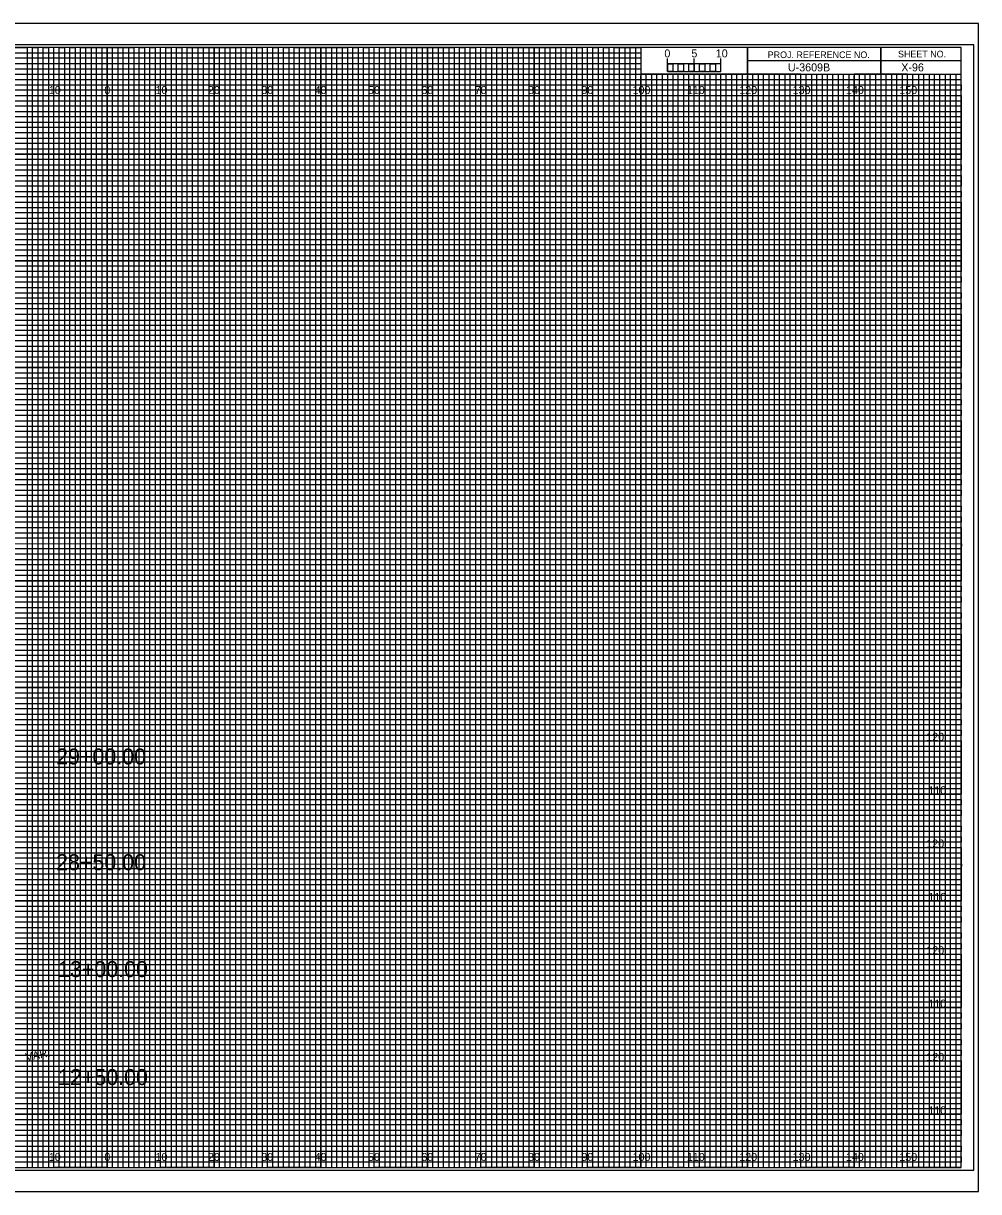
# Model space of a CAD drawing. Extents: x -13 to 323, y -5 to 215.
# Drawn here: x 144.3 to 323.3, y -4.5 to 214.5 of the extents above; entities that cross this region are included whole.
import ezdxf

# ---------------------------------------------------------------- set-up
doc = ezdxf.new("R2010")
doc.units = 0
for name, color, linetype in [('Prop XS Bar Scale Labels', 7, 'Continuous'), ('Prop XS Elevation Labels', 7, 'Continuous'), ('Prop XS Offset Labels', 7, 'Continuous'), ('Prop XS Project Number', 7, 'Continuous'), ('Prop XS Sheet Number', 7, 'Continuous'), ('Prop XS Side Slope Text', 7, 'Continuous'), ('Prop XS Station Labels', 7, 'Continuous'), ('Sheet Cross Section CELL', 7, 'Continuous'), ('Sheet Cross Section Grid Major CELL', 7, 'Continuous'), ('Sheet Cross Section Grid Middle CELL', 7, 'Continuous'), ('Sheet Cross Section Grid Minor 1 CELL', 7, 'Continuous'), ('Sheet Cross Section Grid Minor 2 CELL', 7, 'Continuous'), ('Sheet Cross Section Scale CELL', 7, 'Continuous'), ('Sheet Cutting Line CELL', 7, 'Continuous'), ('Sheet DOT Grid CELL', 7, 'Continuous'), ('Sheet Plot Border Inside CELL', 7, 'Continuous'), ('Sheet Plot Border Outside CELL', 7, 'Continuous')]:
    doc.layers.add(name, color=color, linetype=linetype)

msp = doc.modelspace()

# ---------------------------------------------------------------- linework, layer by layer
at = {"layer": 'Sheet Cross Section CELL'}
for p, q in [((305, 210), (305, 205)), ((305, 205), (305, 210)), ((280, 207.5), (280, 205)), ((320, 207.49), (280, 207.49)), ((280, 205), (320, 205))]:
    msp.add_line(p, q, dxfattribs=at)
for points in [[(320, 210), (0, 210), (0, 0), (320, 0)], [(280, 210), (260, 210), (260, 205.03), (280, 205.03)], [(320, 210), (280, 210), (280, 205), (320, 205)]]:
    msp.add_lwpolyline(points, close=True, dxfattribs=at)
at = {"layer": 'Sheet Cross Section Grid Major CELL'}
for p, q in [((150, 210), (140, 210)), ((150, 0), (150, 210)), ((170, 210), (160, 210)), ((160, 210), (160, 0)), ((170, 0), (170, 210)), ((190, 210), (180, 210)), ((180, 210), (180, 0)), ((190, 0), (190, 210)), ((210, 210), (200, 210)), ((200, 210), (200, 0)), ((210, 0), (210, 210)), ((230, 210), (220, 210)), ((220, 210), (220, 0)), ((230, 0), (230, 210)), ((250, 210), (240, 210)), ((240, 210), (240, 0)), ((250, 0), (250, 210)), ((260, 210), (260, 0)), ((270, 0), (270, 205)), ((290, 205), (280, 205)), ((280, 205), (280, 0)), ((290, 0), (290, 205)), ((310, 205), (300, 205)), ((300, 205), (300, 0)), ((310, 0), (310, 205)), ((160, 0), (150, 0)), ((180, 0), (170, 0)), ((200, 0), (190, 0)), ((220, 0), (210, 0)), ((240, 0), (230, 0)), ((260, 0), (250, 0)), ((280, 0), (270, 0)), ((300, 0), (290, 0)), ((320, 0), (310, 0)), ((320, 0), (320, 0))]:
    msp.add_line(p, q, dxfattribs=at)
for points in [[(0, 200), (320, 200), (320, 190), (0, 190)], [(0, 180), (320, 180), (320, 170), (0, 170)], [(0, 160), (320, 160), (320, 150), (0, 150)], [(0, 140), (320, 140), (320, 130), (0, 130)], [(0, 120), (320, 120), (320, 110), (0, 110)], [(0, 100), (320, 100), (320, 90), (0, 90)], [(0, 80), (320, 80), (320, 70), (0, 70)], [(0, 60), (320, 60), (320, 50), (0, 50)], [(0, 40), (320, 40), (320, 30), (0, 30)], [(0, 20), (320, 20), (320, 10), (0, 10)]]:
    msp.add_lwpolyline(points, dxfattribs=at)
at = {"layer": 'Sheet Cross Section Grid Middle CELL'}
for points in [[(135, 210), (145, 210), (145, 0), (155, 0), (155, 210), (165, 210), (165, 0), (175, 0), (175, 210), (185, 210), (185, 0), (195, 0), (195, 210), (205, 210), (205, 0), (215, 0), (215, 210), (225, 210), (225, 0), (235, 0), (235, 210), (245, 210), (245, 0), (255, 0), (255, 210), (259.93, 210), (260, 210), (260, 205), (264.99, 205), (264.99, 0), (275, 0), (275, 205), (285, 205), (285, 0), (295, 0), (295, 205), (305, 205), (305, 0), (315, 0), (315, 205)], [(0, 205), (275, 205)], [(0, 185), (320, 185), (320, 195), (0, 195)], [(0, 165), (320, 165), (320, 175), (0, 175)], [(0, 145), (320, 145), (320, 155), (0, 155)], [(0, 125), (320, 125), (320, 135), (0, 135)], [(0, 105), (320, 105), (320, 115), (0, 115)], [(0, 85), (320, 85), (320, 95), (0, 95)], [(0, 65), (320, 65), (320, 75), (0, 75)], [(0, 45), (320, 45), (320, 55), (0, 55)], [(0, 25), (320, 25), (320, 35), (0, 35)], [(0, 5), (320, 5), (320, 15), (0, 15)]]:
    msp.add_lwpolyline(points, dxfattribs=at)
at = {"layer": 'Sheet Cross Section Grid Minor 1 CELL'}
for p, q in [((0, 209), (260, 209)), ((260, 209), (260, 207.98)), ((260, 207.98), (0, 207.98)), ((0, 207), (260, 207)), ((260, 205.89), (0, 205.89)), ((260, 207), (260, 205.89)), ((0, 204), (320, 204))]:
    msp.add_line(p, q, dxfattribs=at)
for points in [[(0, 203), (270, 203), (320, 203), (320, 202), (0, 202)], [(0, 201), (320, 201), (320, 199), (0, 199)], [(0, 198), (320, 198), (320, 197), (0, 196.98)], [(0, 196), (320, 196), (320, 194), (0, 194)], [(0, 193), (320, 193), (320, 192), (0, 192)], [(0, 191), (320, 191), (320, 189), (0, 189)], [(0, 188), (320, 188), (320, 187), (0, 187)], [(0, 186), (320, 186), (320, 184), (0, 184)], [(0, 183), (320, 183), (320, 182), (0, 182)], [(0, 181), (320, 181), (320, 179), (0, 179)], [(0, 178), (320, 178), (320, 177), (0, 177)], [(0, 176), (320, 176), (320, 173.95), (320, 173), (320, 172), (0, 172)], [(0, 174), (320, 174), (320, 173), (0, 173)], [(0, 171), (320, 171), (320, 169), (0, 169.03)], [(0, 169.03), (320, 169), (320, 168), (0, 168)], [(0, 167), (320, 167), (320, 166), (0, 166)], [(0, 164), (320, 164), (320, 163), (0, 163)], [(0, 162), (320, 162), (320, 161), (0, 161)], [(-0.07, 158.89), (320, 158.89), (320, 157.88), (-0.07, 157.88)], [(0, 157), (320, 157), (320, 156), (0, 156)], [(0, 154), (320, 154), (320, 153), (0, 153)], [(0, 152), (320, 152), (320, 151), (0, 151)], [(0, 149), (320, 149), (320, 148), (0, 148)], [(0, 147), (320, 147), (320, 146), (0, 146)], [(0, 144), (320, 144), (320, 143), (0, 143)], [(0, 142), (320, 142), (320, 141), (0, 141)], [(0, 139), (320, 139), (319.99, 137.98), (0, 138)], [(0, 137), (320, 137), (320, 136), (0, 136)], [(0, 134), (320, 134), (320, 133), (0, 133)], [(0, 132), (320, 132), (320, 131), (0, 131)], [(0, 129), (320, 129), (320, 128), (0, 128)], [(0, 127), (320, 127), (320, 126), (0, 126)], [(0, 124), (320, 124), (320, 123), (0, 123)], [(0, 122), (320, 122), (320, 121), (0, 121)], [(0, 119), (320, 119), (320, 118), (0, 118)], [(0, 116.99), (320.07, 116.91), (320, 116), (0, 116)], [(0, 114), (320, 114), (320, 113), (0, 113)], [(0, 112), (320, 112), (320, 111), (0, 111)], [(0, 109), (320, 109), (320, 108), (0, 108)], [(0, 107), (320, 107), (320, 106), (0, 106)], [(0, 104), (320, 104), (320, 103), (0, 103)], [(0, 102), (320, 102), (320, 101), (0, 101)], [(0, 99), (320, 99), (320, 98), (0, 98)], [(0, 97), (320, 97), (320, 96), (0, 96)], [(0, 94), (320, 94), (320, 93), (0, 93)], [(0, 92), (320, 92), (320, 91), (0, 91)], [(0, 89), (320, 89), (320, 88), (0, 88)], [(0, 87), (320, 87), (320, 86), (0, 86)], [(0, 84), (320, 84), (320, 83), (0, 83)], [(0, 82), (320, 82), (320, 81), (0, 81)], [(0, 79), (320, 79), (319.99, 77.98), (0, 78)], [(0, 77), (320, 77), (320, 76), (0, 76)], [(0, 74), (320, 74), (320, 73), (0, 73)], [(0, 72), (320, 72), (320, 71), (0, 71)], [(0, 69), (320, 69), (320, 68), (0, 68)], [(0, 67), (320, 67), (320, 66), (0, 66)], [(0, 64), (320, 64), (320, 63), (0, 63)], [(0, 62), (320, 62), (320, 61), (0, 61)], [(0, 59), (320, 59), (320, 58), (0, 58)], [(0, 56.99), (320.07, 56.91), (320, 56), (0, 56)], [(0, 54), (320, 54), (320, 53), (0, 53)], [(0, 52), (320, 52), (320, 51), (0, 51)], [(0, 49), (320, 49), (320, 48), (0, 48)], [(0, 47), (320, 47), (320, 46), (0, 46)], [(0, 44), (320, 44), (320, 43), (0, 43)], [(0, 42), (320, 42), (320, 41), (0, 41)], [(0, 39), (320, 39), (320, 38), (0, 38)], [(0, 37), (320, 37), (320, 36), (0, 36)], [(0, 34), (320, 34), (320, 33), (0, 33)], [(0, 32), (320, 32), (320, 31), (0, 31)], [(0, 29), (320, 29), (320, 28), (0, 28)], [(0, 27), (320, 27), (320, 26), (0, 26)], [(0, 24), (320, 24), (320, 23), (0, 23)], [(0, 22), (320, 22), (320, 21), (0, 21)], [(0, 19), (320, 19), (320, 18), (0, 18)], [(0, 17), (320, 17), (320, 16), (0, 16)], [(0, 14), (320, 14), (320, 13), (0, 13)], [(0, 12), (320, 12), (320, 11), (0, 11)], [(0, 9), (320, 9), (320, 8), (0, 8)], [(0, 7), (320, 7), (320, 6), (0, 6)], [(0, 4), (320, 4), (320, 3), (0, 3)], [(0, 2), (320, 2), (320, 1), (0, 1)]]:
    msp.add_lwpolyline(points, dxfattribs=at)
at = {"layer": 'Sheet Cross Section Grid Minor 2 CELL'}
for p, q in [((267, 205), (266.01, 205)), ((266.01, 205), (266.01, 0)), ((267, 0), (267, 205)), ((269, 205), (268, 205)), ((268, 205), (268, 0)), ((269, 0), (269, 205)), ((266.01, 0), (265, 0)), ((268, 0), (267, 0))]:
    msp.add_line(p, q, dxfattribs=at)
for points in [[(145, 0), (146, 0), (146, 210), (147, 210), (147, 0)], [(147, 0), (148, 0), (148, 210), (149, 210), (149, 0)], [(150, 0), (151, 0), (151, 210), (152, 210), (152, 0)], [(152, 0), (153, 0), (153, 210), (154, 210), (154, 0)], [(155, 0), (156, 0), (156, 210), (157, 210), (157, 0)], [(157, 0), (158, 0), (158, 210), (159, 210), (159, 0)], [(160, 0), (161, 0), (161, 210), (162, 210), (162, 0)], [(162, 0), (163, 0), (163, 210), (164, 210), (164, 0)], [(165, 0), (166, 0), (166, 210), (167, 210), (167, 0)], [(167, 0), (168, 0), (168, 210), (169, 210), (169, 0)], [(170, 0), (171, 0), (171, 210), (172, 210), (172, 0)], [(172, 0), (173, 0), (173, 210), (174, 210), (174, 0)], [(175, 0), (176, 0), (176, 210), (177, 210), (177, 0)], [(177, 0), (178, 0), (178, 210), (179, 210), (179, 0)], [(180, 0), (181, 0), (181, 210), (182, 210), (182, 0)], [(182, 0), (183, 0), (183, 210), (184, 210), (184, 0)], [(185, 0), (186, 0), (186, 210), (187, 210), (187, 0)], [(187, 0), (188, 0), (188, 210), (189, 210), (189, 0)], [(190, 0), (191, 0), (191, 210), (192, 210), (192, 0)], [(192, 0), (193, 0), (193, 210), (194, 210), (194, 0)], [(195, 0), (196, 0), (196, 210), (197, 210), (197, 0)], [(197, 0), (198, 0), (198, 210), (199, 210), (199, 0)], [(200, 0), (201, 0), (201, 210), (202, 210), (202, 0)], [(202, 0), (203, 0), (203, 210), (204, 210), (204, 0)], [(205, 0), (206, 0), (206, 210), (207, 210), (207, 0)], [(207, 0), (208, 0), (208, 210), (209, 210), (209, 0)], [(210, 0), (211, 0), (211, 210), (212, 210), (212, 0)], [(212, 0), (213, 0), (213, 210), (214, 210), (214, 0)], [(215, 0), (216, 0), (216, 210), (217, 210), (217, 0)], [(217, 0), (218, 0), (218, 210), (219, 210), (219, 0)], [(220, 0), (221, 0), (221, 210), (222, 210), (222, 0)], [(222, 0), (223, 0), (223, 210), (224, 210), (224, 0)], [(225, 0), (226, 0), (226, 210), (227, 210), (227, 0)], [(227, 0), (228, 0), (228, 210), (229, 210), (229, 0)], [(230, 0), (231, 0), (231, 210), (232, 210), (232, 0)], [(232, 0), (233, 0), (233, 210), (234, 210), (234, 0)], [(235, 0), (236, 0), (236, 210), (237, 210), (237, 0)], [(237, 0), (238, 0), (238, 210), (239, 210), (239, 0)], [(240, 0), (241, 0), (241, 210), (242, 210), (242, 0)], [(242, 0), (243, 0), (243, 210), (244, 210), (244, 0)], [(245, 0), (246, 0), (246, 210), (247, 210), (247, 0)], [(247, 0), (248, 0), (248, 210), (249, 210), (249, 0)], [(250, 0), (251, 0), (251, 210), (252, 210), (252, 0)], [(252, 0), (253, 0), (253, 210), (254, 210), (254, 0)], [(255, 0), (256, 0), (256, 210), (257, 210), (257, 0)], [(257, 0), (258, 0), (258, 210), (259, 210), (259, 0)], [(260, 0), (261, 0), (261, 205), (262.02, 205), (262.02, 0)], [(262, 0), (263, 0), (263, 205), (263.99, 205), (263.99, 0)], [(270, 0), (270.98, 0), (270.98, 205), (272, 205), (272, 0)], [(272, 0), (273, 0), (273, 205), (274.05, 205), (274.05, 0)], [(275, 0), (276, 0), (276, 205), (277, 205), (277, 0)], [(277, 0), (278, 0), (278, 205), (279, 205), (279, 0)], [(280, 0), (281, 0), (281, 205), (282, 205), (282, 0)], [(282, 0), (283, 0), (283, 205), (284, 205), (284, 0)], [(285, 0), (286, 0), (286, 205), (287, 205), (287, 0)], [(287, 0), (288, 0), (288, 205), (289, 205), (289, 0)], [(290, 0), (291, 0), (291, 205), (292, 205), (292, 0)], [(292, 0), (293, 0), (293, 205), (294, 205), (294, 0)], [(295, 0), (296, 0), (296, 205), (297, 205), (297, 0)], [(297, 0), (298, 0), (298, 205), (299, 205), (299, 0)], [(300, 0), (301, 0), (301, 205), (302, 205), (302, 0)], [(302, 0), (303, 0), (303, 205), (304, 205), (304, 0)], [(305, 0), (306, 0), (306, 205), (307, 205), (307, 0)], [(307, 0), (308, 0), (308, 205), (309, 205), (309, 0)], [(310, 0), (311, 0), (311, 205), (312, 205), (312, 0)], [(312, 0), (313, 0), (313, 205), (314, 205), (314, 0)], [(315, 0), (316, 0), (316, 205), (317, 205), (317, 0)], [(317, 0), (318, 0), (318, 205), (319, 205), (319, 0)]]:
    msp.add_lwpolyline(points, dxfattribs=at)
at = {"layer": 'Sheet Cross Section Scale CELL'}
for p, q in [((265, 205.49), (265, 207.9)), ((265, 206.9), (265, 207.9)), ((270, 205.49), (270, 207.9)), ((275, 205.49), (275, 207.9)), ((275, 206.9), (275, 207.9))]:
    msp.add_line(p, q, dxfattribs=at)
for points in [[(275, 206.9), (265, 206.9), (265, 205.49), (275, 205.49)], [(265, 206.9), (266, 206.9), (266, 205.49), (265, 205.49)], [(267, 206.9), (268, 206.9), (268, 205.49), (267, 205.49)], [(269, 206.9), (270, 206.9), (270, 205.49), (269, 205.49)], [(271, 206.9), (272, 206.9), (272, 205.49), (271, 205.49)], [(273, 206.9), (274, 206.9), (274, 205.49), (273, 205.49)]]:
    msp.add_lwpolyline(points, close=True, dxfattribs=at)
at = {"layer": 'Sheet Cutting Line CELL'}
for p, q in [((323.3, 214.5), (-13.4, 214.5)), ((-13.4, -4.5), (323.3, -4.5))]:
    msp.add_line(p, q, dxfattribs=at)
at = {"layer": 'Sheet DOT Grid CELL'}
for p, q in [((150, 0), (150, 210)), ((160, 0), (160, 210)), ((170, 0), (170, 210)), ((180, 0), (180, 210)), ((190, 0), (190, 210)), ((200, 0), (200, 210)), ((210, 0), (210, 210)), ((220, 0), (220, 210)), ((230, 0), (230, 210)), ((240, 0), (240, 210)), ((250, 0), (250, 210)), ((260, 0), (260, 204.69)), ((270, 0), (270, 204.69)), ((280, 0), (280, 204.69)), ((290, 0), (290, 204.69)), ((300, 0), (300, 204.69)), ((310, 0), (310, 204.69)), ((0, 200), (320, 200)), ((0, 190), (320, 190)), ((0, 180), (320, 180)), ((0, 170), (320, 170)), ((0, 160), (320, 160)), ((0, 150), (320, 150)), ((0, 140), (320, 140)), ((0, 130), (320, 130)), ((0, 120), (320, 120)), ((0, 110), (320, 110)), ((0, 100), (320, 100)), ((0, 90), (320, 90)), ((0, 80), (320, 80)), ((0, 70), (320, 70)), ((0, 60), (320, 60)), ((0, 50), (320, 50)), ((0, 40), (320, 40)), ((0, 30), (320, 30)), ((0, 20), (320, 20)), ((0, 10), (320, 10))]:
    msp.add_line(p, q, dxfattribs=at)
at = {"layer": 'Sheet Plot Border Inside CELL'}
msp.add_lwpolyline([(-10.8, -0.5), (322.4, -0.5), (322.4, 210.5), (-10.8, 210.5)], close=True, dxfattribs=at)
at = {"layer": 'Sheet Plot Border Outside CELL'}
msp.add_lwpolyline([(-13.4, -4.5), (323.3, -4.5), (323.3, 214.5), (-13.4, 214.5)], close=True, dxfattribs=at)

# ---------------------------------------------------------------- texts
at = {"layer": 'Prop XS Bar Scale Labels'}
for s, p in [('5', (269.47, 208.12)), ('10', (274.04, 208.12))]:
    msp.add_text(s, height=1.5, dxfattribs=at).set_placement(p)
at = {"layer": 'Prop XS Elevation Labels'}
for s, p in [('120', (313.5, 80)), ('110', (313.88, 70)), ('120', (313.5, 60)), ('110', (313.88, 50)), ('120', (313.5, 40)), ('110', (313.88, 30)), ('120', (313.5, 20)), ('110', (313.88, 10))]:
    msp.add_text(s, height=1.5, dxfattribs=at).set_placement(p)
at = {"layer": 'Prop XS Offset Labels'}
for s, p in [('10', (149.04, 201.25)), ('0', (159.45, 201.25)), ('0', (159.45, 201.25)), ('10', (169.04, 201.25)), ('20', (178.86, 201.25)), ('30', (188.86, 201.25)), ('40', (198.86, 201.25)), ('50', (208.86, 201.25)), ('60', (218.86, 201.25)), ('70', (228.86, 201.25)), ('80', (238.86, 201.25)), ('90', (248.86, 201.25)), ('100', (258.44, 201.25)), ('110', (268.62, 201.25)), ('120', (278.44, 201.25)), ('130', (288.44, 201.25)), ('140', (298.44, 201.25)), ('150', (308.44, 201.25)), ('10', (149.04, 1.25)), ('0', (159.45, 1.25)), ('0', (159.45, 1.25)), ('10', (169.04, 1.25)), ('20', (178.86, 1.25)), ('30', (188.86, 1.25)), ('40', (198.86, 1.25)), ('50', (208.86, 1.25)), ('60', (218.86, 1.25)), ('70', (228.86, 1.25)), ('80', (238.86, 1.25)), ('90', (248.86, 1.25)), ('100', (258.44, 1.25)), ('110', (268.62, 1.25)), ('120', (278.44, 1.25)), ('130', (288.44, 1.25)), ('140', (298.44, 1.25)), ('150', (308.44, 1.25))]:
    msp.add_text(s, height=1.5, dxfattribs=at).set_placement(p)
at = {"layer": 'Prop XS Project Number'}
msp.add_text('U-3609B', height=1.5, dxfattribs=at).set_placement((287.56, 205.5))
at = {"layer": 'Prop XS Sheet Number'}
msp.add_text('X-96', height=1.5, dxfattribs=at).set_placement((308.8, 205.5))
at = {"layer": 'Prop XS Side Slope Text'}
msp.add_text('VAR.', height=1.5, rotation=11.383, dxfattribs=at).set_placement((144.83, 19.94))
at = {"layer": 'Prop XS Station Labels'}
for s, p in [('29+00.00', (150.41, 75.57)), ('28+50.00', (150.41, 55.75)), ('13+00.00', (150.77, 35.72)), ('12+50.00', (150.77, 15.48))]:
    msp.add_text(s, height=3, dxfattribs=at).set_placement(p)
at = {"layer": 'Sheet Cross Section CELL'}
for s, p in [('PROJ. REFERENCE NO.', (283.77, 207.99)), ('SHEET NO.', (308.19, 208.12))]:
    msp.add_text(s, height=1.25, dxfattribs=at).set_placement(p)
at = {"layer": 'Sheet Cross Section Scale CELL'}
msp.add_text('0', height=1.5, dxfattribs=at).set_placement((264.41, 208.12))

doc.saveas('drawing.dxf')
